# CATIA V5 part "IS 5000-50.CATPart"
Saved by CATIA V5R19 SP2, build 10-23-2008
Part number: IS 5000-50
Bounding box of the stored display mesh (mm): x -59.975 to 59.975, y -59.975 to 59.975, z 0 to 240
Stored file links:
  C:\Users\Bora\Desktop\3D Katı model\IS serisi\IS 5000\IS 5000-50.CATPart
  C:\Program Files\Dassault Systemes\B19\intel_a\reffiles\standard\MetricThickPitch.txt
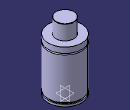
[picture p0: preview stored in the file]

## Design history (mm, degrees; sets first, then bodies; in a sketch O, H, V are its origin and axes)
Body1 (main body)
  Sketch1 on yz-plane, origin (0, 0, 0), H (0, 1, 0), V (0, 0, 1)
    point P1 (60, 167)
    point P4 (60, 162)
    point P7 (32.5, 239)
    point P9 (32.5, 239)
    point P13 (60, 167)
    point P14 (60, 162)
    line L1 (60, 167) -> (60, 187)
    line L2 (60, 13) -> (60, 162)
    line L3 (56, 13) -> (56, 8)
    arc A1 centre (31.5, 239) radius 1 from (32.5, 239) to (31.5, 240) ccw
    line L4 (32.5, 239) -> (32.5, 187)
    line L5 (60, 0) -> (60, 8)
    arc A2 centre (60, 164.5) radius 2.5 from (60, 167) to (60, 162) ccw
    line L6 (31.5, 240) -> (0, 240)
    point P15 (0, 240)
    line L7 (32.5, 187) -> (60, 187)
    line L8 (0, 0) -> (60, 0)
    line L9 (56, 13) -> (60, 13)
    line L10 (56, 8) -> (60, 8)
    coincidence: P15 V, P1 P13, P4 P14, P7 P9
    tangency: L6 A1
    horizontal: L7 H, L8 H, L9 H, L10 H
  Shaft1: profile Sketch1, axis Sketch1.V, angle 360
  Sketch2 on face of Shaft1 from Sketch1.L8, origin (0, 0, 0), H (1, 0, 0), V (0, -1, 0)
    point P1 (40, 0)
    distance P1 V = 40
  Hole1: placed by Sketch2, at (40, 0, 0) direction (0, 0, 1), diameter 8.376, depth 16, threaded "M10", thread diameter 10, thread depth 16, pitch 1.5
  CircPattern1: of Hole1, instances 4, angular step 90, axis from xy-plane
